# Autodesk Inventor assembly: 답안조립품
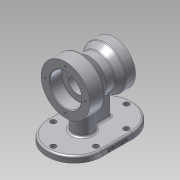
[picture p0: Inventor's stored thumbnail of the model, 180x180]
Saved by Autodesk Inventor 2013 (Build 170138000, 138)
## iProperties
Created: 2020-01
Part Number: 답안조립품
Document SubType Name: Assembly
Designer: Administrator
Author: Administrator
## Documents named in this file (2)
- C:\Users\Administrator\Desktop\700104V1018\답안조립품.iam
- C:\Users\Administrator\Desktop\700104V1018\본체.ipt
